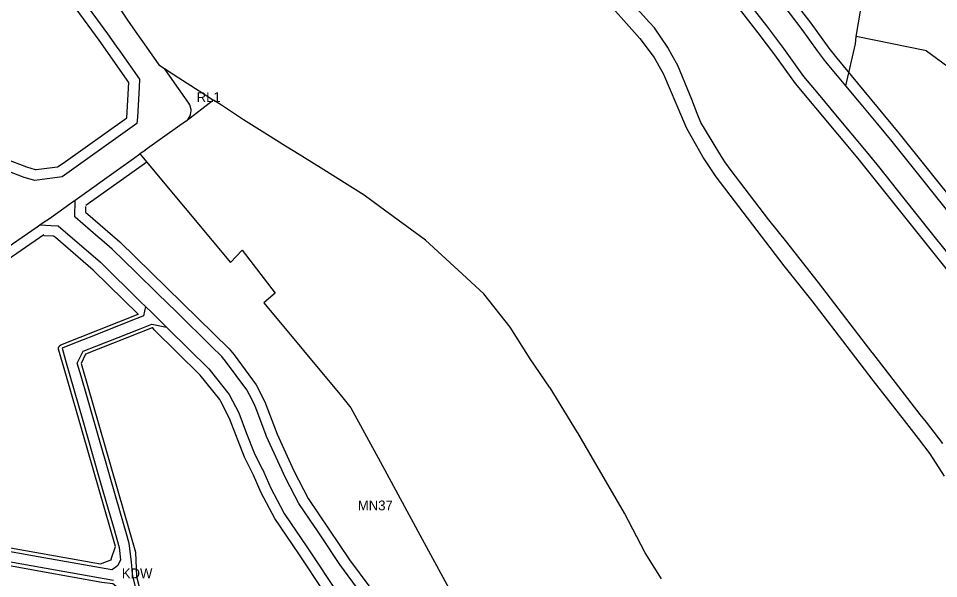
# Model space of a CAD drawing. Extents: x 7428103 to 7431580, y 5545880 to 5549002.
# Drawn here: x 7430217 to 7430738, y 5546912 to 5547228 of the extents above; entities that cross this region are included whole.
import ezdxf

# ---------------------------------------------------------------- set-up
doc = ezdxf.new("R2010")
doc.units = 0
for name, color, linetype in [('CZ_L_linie rozgraniczające tereny o różnym przeznaczeniu oraz różnych warunkach ich zabudowy i zagospodarowania', 7, 'Continuous'), ('CZ_L_maksymalne nieprzekraczalne linie zabudowy', 7, 'Continuous'), ('CZ_L_opisy_linie rozgraniczające tereny o różnym przeznaczeniu oraz różnych warunkach ich zabudowy i zagospodarowania', 7, 'Continuous')]:
    doc.layers.add(name, color=color, linetype=linetype)

msp = doc.modelspace()

# ---------------------------------------------------------------- linework, layer by layer
at = {"layer": 'CZ_L_linie rozgraniczające tereny o różnym przeznaczeniu oraz różnych warunkach ich zabudowy i zagospodarowania'}
for p, q in [((7430212.67, 5547295.01), (7430267.72, 5547219.77)), ((7430691.24, 5547218.28), (7430696.26, 5547247.28)), ((7430629.65, 5547238.08), (7430640.5, 5547224.17)), ((7430660.77, 5547222.18), (7430647.47, 5547239.67)), ((7430274.38, 5547234.22), (7430279.05, 5547227.49)), ((7430553.53, 5547234.13), (7430561.35, 5547225.52)), ((7430574.28, 5547226.17), (7430567.4, 5547233.85)), ((7430279.05, 5547227.49), (7430283.4, 5547221.22)), ((7430561.35, 5547225.52), (7430568.82, 5547217.12)), ((7430577.08, 5547223.04), (7430574.28, 5547226.17)), ((7430283.4, 5547221.22), (7430289.75, 5547212.08)), ((7430584.64, 5547212.05), (7430577.08, 5547223.04)), ((7430640.5, 5547224.17), (7430650.12, 5547211.32)), ((7430669.43, 5547210.13), (7430660.77, 5547222.18)), ((7430267.72, 5547219.77), (7430272.66, 5547212.75)), ((7430568.82, 5547217.12), (7430576.93, 5547206.31)), ((7430690.94, 5547214.14), (7430691.24, 5547218.28)), ((7430731.04, 5547210.13), (7430691.24, 5547218.28)), ((7430272.66, 5547212.75), (7430274.72, 5547209.82)), ((7430274.72, 5547209.82), (7430285.86, 5547194.01)), ((7430289.75, 5547212.08), (7430296.63, 5547202.17)), ((7430587.23, 5547207.47), (7430584.64, 5547212.05)), ((7430650.12, 5547211.32), (7430661.48, 5547195.53)), ((7430673.89, 5547204.06), (7430669.43, 5547210.13)), ((7430685.45, 5547190.23), (7430690.94, 5547214.14)), ((7430731, 5547209.91), (7430731.04, 5547210.13)), ((7430746.02, 5547199.03), (7430731, 5547209.91)), ((7430576.93, 5547206.31), (7430582.32, 5547196.97)), ((7430590.35, 5547201.86), (7430587.23, 5547207.47)), ((7430296.63, 5547202.17), (7430299.94, 5547200.07)), ((7430299.94, 5547200.07), (7430308.09, 5547194.89)), ((7430598.18, 5547182.53), (7430590.35, 5547201.86)), ((7430680.6, 5547196.03), (7430673.89, 5547204.06)), ((7430308.09, 5547194.89), (7430319.59, 5547187.56)), ((7430582.32, 5547196.97), (7430592.98, 5547171.71)), ((7430661.48, 5547195.53), (7430669.68, 5547185.71)), ((7430685.45, 5547190.23), (7430680.6, 5547196.03)), ((7430285.56, 5547189.32), (7430284.67, 5547172.63)), ((7430285.86, 5547194.01), (7430285.56, 5547189.32)), ((7430693.07, 5547181.11), (7430685.45, 5547190.23)), ((7430319.59, 5547187.56), (7430327.65, 5547182.26)), ((7430669.68, 5547185.71), (7430680.43, 5547172.85)), ((7430327.65, 5547182.26), (7430312, 5547170.24)), ((7430332.14, 5547179.31), (7430327.65, 5547182.26)), ((7430344.63, 5547171.1), (7430332.14, 5547179.31)), ((7430601.33, 5547174.76), (7430598.18, 5547182.53)), ((7430703.47, 5547168.66), (7430693.07, 5547181.11)), ((7430603.45, 5547169.52), (7430601.33, 5547174.76)), ((7430284.3, 5547168.95), (7430241.96, 5547138.87)), ((7430284.67, 5547172.63), (7430284.3, 5547168.95)), ((7430311.87, 5547170.15), (7430307.34, 5547166.92)), ((7430311.95, 5547170.21), (7430311.87, 5547170.15)), ((7430312, 5547170.24), (7430311.95, 5547170.21)), ((7430358.25, 5547162.54), (7430344.63, 5547171.1)), ((7430592.98, 5547171.71), (7430595.2, 5547166.46)), ((7430606.07, 5547165.24), (7430603.45, 5547169.52)), ((7430680.43, 5547172.85), (7430696.82, 5547153.23)), ((7430711.58, 5547158.94), (7430703.47, 5547168.66)), ((7430307.3, 5547166.89), (7430295.67, 5547158.63)), ((7430307.34, 5547166.92), (7430307.3, 5547166.89)), ((7430595.2, 5547166.46), (7430605.02, 5547149.12)), ((7430614.18, 5547151.8), (7430606.07, 5547165.24)), ((7430295.67, 5547158.63), (7430288.98, 5547153.88)), ((7430368.34, 5547156.29), (7430358.25, 5547162.54)), ((7430716.84, 5547152.34), (7430711.58, 5547158.94)), ((7430288.95, 5547153.85), (7430286.06, 5547151.81)), ((7430288.98, 5547153.88), (7430288.95, 5547153.85)), ((7430373.71, 5547152.95), (7430368.34, 5547156.29)), ((7430388.49, 5547143.78), (7430373.71, 5547152.95)), ((7430696.82, 5547153.23), (7430704.54, 5547143.71)), ((7430220.62, 5547138.54), (7430195.21, 5547148.12)), ((7430273.98, 5547143.22), (7430282.38, 5547149.19)), ((7430282.38, 5547149.19), (7430282.46, 5547149.26)), ((7430282.46, 5547149.26), (7430286.06, 5547151.81)), ((7430286.06, 5547151.81), (7430337.18, 5547090.38)), ((7430605.02, 5547149.12), (7430611.9, 5547138.93)), ((7430616.86, 5547147.35), (7430614.18, 5547151.8)), ((7430620.54, 5547142.52), (7430616.86, 5547147.35)), ((7430726.71, 5547139.98), (7430716.84, 5547152.34)), ((7430249.37, 5547125.74), (7430273.98, 5547143.22)), ((7430412.85, 5547128.44), (7430388.49, 5547143.78)), ((7430641.91, 5547114.51), (7430620.54, 5547142.52)), ((7430704.54, 5547143.71), (7430717.38, 5547127.62)), ((7430226.55, 5547136.8), (7430220.62, 5547138.54)), ((7430241.96, 5547138.87), (7430226.55, 5547136.8)), ((7430611.9, 5547138.93), (7430650.34, 5547088.54)), ((7430737.11, 5547126.94), (7430726.71, 5547139.98)), ((7430421.52, 5547122.12), (7430412.85, 5547128.44)), ((7430717.38, 5547127.62), (7430734.48, 5547106.2)), ((7430742.39, 5547120.33), (7430737.11, 5547126.94)), ((7430242.96, 5547121.18), (7430248.43, 5547125.07)), ((7430248.43, 5547125.07), (7430248.9, 5547125.4)), ((7430248.9, 5547125.4), (7430249.33, 5547125.7)), ((7430249.17, 5547116.22), (7430249.33, 5547125.7)), ((7430249.33, 5547125.7), (7430249.37, 5547125.74)), ((7430447.52, 5547103.14), (7430421.52, 5547122.12)), ((7430234.78, 5547115.41), (7430242.88, 5547121.11)), ((7430242.88, 5547121.11), (7430242.96, 5547121.18)), ((7430249.19, 5547116.2), (7430249.17, 5547116.22)), ((7430249.3, 5547116.1), (7430249.19, 5547116.2)), ((7430262.41, 5547104.83), (7430249.3, 5547116.1)), ((7430227.89, 5547110.67), (7430229.47, 5547111.75)), ((7430229.47, 5547111.75), (7430231.82, 5547113.37)), ((7430229.47, 5547111.75), (7430235.72, 5547111.38)), ((7430231.82, 5547113.37), (7430234.77, 5547115.4)), ((7430234.77, 5547115.4), (7430234.77, 5547115.41)), ((7430234.77, 5547115.41), (7430234.78, 5547115.41)), ((7430235.72, 5547111.38), (7430239.75, 5547111.13)), ((7430239.75, 5547111.13), (7430263.65, 5547090.57)), ((7430651.95, 5547102), (7430641.91, 5547114.51)), ((7430186.16, 5547081.91), (7430227.89, 5547110.67)), ((7430734.48, 5547106.2), (7430748.41, 5547088.89)), ((7430264.46, 5547103.07), (7430262.41, 5547104.83)), ((7430270.3, 5547098.04), (7430264.46, 5547103.07)), ((7430466.04, 5547086.19), (7430447.52, 5547103.14)), ((7430660.92, 5547090.58), (7430651.95, 5547102)), ((7430270.39, 5547097.92), (7430270.3, 5547098.04)), ((7430270.53, 5547097.83), (7430270.39, 5547097.92)), ((7430283.49, 5547085.16), (7430270.53, 5547097.83)), ((7430337.18, 5547090.38), (7430343.87, 5547097.36)), ((7430343.87, 5547097.36), (7430362.49, 5547073.08)), ((7430263.65, 5547090.57), (7430286.41, 5547068.31)), ((7430669.94, 5547079.13), (7430660.92, 5547090.58)), ((7430296.1, 5547072.82), (7430283.49, 5547085.16)), ((7430480.56, 5547072.8), (7430466.04, 5547086.19)), ((7430650.34, 5547088.54), (7430666.18, 5547068.85)), ((7430692.81, 5547049.44), (7430669.94, 5547079.13)), ((7430306.65, 5547062.49), (7430296.1, 5547072.82)), ((7430362.49, 5547073.08), (7430356.04, 5547067.71)), ((7430495.45, 5547053.89), (7430480.56, 5547072.8)), ((7430286.41, 5547068.31), (7430289.19, 5547065.58)), ((7430289.19, 5547065.58), (7430288.06, 5547060.24)), ((7430292.75, 5547062.1), (7430289.19, 5547065.58)), ((7430356.04, 5547067.71), (7430400.03, 5547014.84)), ((7430666.18, 5547068.85), (7430683.58, 5547046.14)), ((7430284.84, 5547058.96), (7430282.8, 5547058.16)), ((7430288.06, 5547060.24), (7430284.84, 5547058.96)), ((7430297.47, 5547057.48), (7430292.75, 5547062.1)), ((7430306.66, 5547062.49), (7430306.65, 5547062.49)), ((7430306.66, 5547062.48), (7430306.66, 5547062.49)), ((7430326.59, 5547042.92), (7430306.66, 5547062.48)), ((7430282.8, 5547058.16), (7430259.73, 5547049.02)), ((7430286.2, 5547053.05), (7430288.08, 5547053.79)), ((7430288.08, 5547053.79), (7430292.77, 5547055.63)), ((7430292.77, 5547055.63), (7430301.11, 5547053.91)), ((7430301.11, 5547053.91), (7430297.47, 5547057.48)), ((7430301.11, 5547053.91), (7430302, 5547053.05)), ((7430506.88, 5547036.04), (7430495.45, 5547053.89)), ((7430259.73, 5547049.02), (7430248.09, 5547044.41)), ((7430273.79, 5547048.14), (7430286.2, 5547053.05)), ((7430302, 5547053.05), (7430325.08, 5547030.39)), ((7430700.35, 5547039.64), (7430692.81, 5547049.44)), ((7430248.09, 5547044.41), (7430241.94, 5547042.03)), ((7430253.91, 5547040.26), (7430261.6, 5547043.31)), ((7430261.6, 5547043.31), (7430273.79, 5547048.14)), ((7430683.58, 5547046.14), (7430700.73, 5547023.82)), ((7430241.94, 5547042.03), (7430244.32, 5547033.66)), ((7430250.6, 5547033.56), (7430253.91, 5547040.26)), ((7430332.31, 5547037.31), (7430326.59, 5547042.92)), ((7430700.63, 5547039.28), (7430700.35, 5547039.64)), ((7430715.32, 5547020.17), (7430700.63, 5547039.28)), ((7430244.32, 5547033.66), (7430246.35, 5547026.52)), ((7430252.73, 5547026.16), (7430250.6, 5547033.56)), ((7430332.35, 5547037.25), (7430332.31, 5547037.31)), ((7430332.72, 5547036.85), (7430332.35, 5547037.25)), ((7430334.51, 5547034.6), (7430332.72, 5547036.85)), ((7430346.48, 5547018.5), (7430334.51, 5547034.6)), ((7430517.67, 5547020), (7430506.88, 5547036.04)), ((7430325.08, 5547030.39), (7430336.58, 5547015.88)), ((7430246.35, 5547026.52), (7430253.7, 5547001.07)), ((7430256.27, 5547013.86), (7430252.73, 5547026.16)), ((7430700.73, 5547023.82), (7430718.34, 5547001.14)), ((7430347.95, 5547015.65), (7430346.48, 5547018.5)), ((7430518.08, 5547019.52), (7430517.67, 5547020)), ((7430533.6, 5546994.45), (7430518.08, 5547019.52)), ((7430727.39, 5547004.45), (7430715.32, 5547020.17)), ((7430263.11, 5546990.06), (7430256.27, 5547013.86)), ((7430336.58, 5547015.88), (7430341.98, 5547005.42)), ((7430351, 5547009.74), (7430347.95, 5547015.65)), ((7430400.03, 5547014.84), (7430405.25, 5547008.39)), ((7430351.07, 5547009.45), (7430351, 5547009.74)), ((7430351.23, 5547009.23), (7430351.07, 5547009.45)), ((7430357.26, 5546993.31), (7430351.23, 5547009.23)), ((7430405.25, 5547008.39), (7430421.95, 5546977.92)), ((7430341.98, 5547005.42), (7430346.36, 5546993.86)), ((7430731.1, 5547000.24), (7430727.39, 5547004.45)), ((7430253.7, 5547001.07), (7430259.44, 5546981.09)), ((7430718.34, 5547001.14), (7430726.24, 5546990.95)), ((7430737.75, 5546991.41), (7430731.1, 5547000.24)), ((7430346.36, 5546993.86), (7430350.64, 5546982.93)), ((7430357.69, 5546992.16), (7430357.26, 5546993.31)), ((7430368.33, 5546968.65), (7430357.69, 5546992.16)), ((7430533.71, 5546994.25), (7430533.6, 5546994.45)), ((7430540.01, 5546983.39), (7430533.71, 5546994.25)), ((7430740.2, 5546988.17), (7430737.75, 5546991.41)), ((7430266.48, 5546978.32), (7430263.11, 5546990.06)), ((7430726.24, 5546990.95), (7430732.96, 5546982.28)), ((7430259.44, 5546981.09), (7430263.42, 5546967.23)), ((7430350.64, 5546982.93), (7430355.26, 5546973.58)), ((7430560.1, 5546948.76), (7430540.01, 5546983.39)), ((7430732.96, 5546982.28), (7430740.94, 5546969.76)), ((7430272.51, 5546957.34), (7430266.48, 5546978.32)), ((7430421.95, 5546977.92), (7430445.69, 5546934.1)), ((7430355.26, 5546973.58), (7430355.37, 5546973.55)), ((7430355.37, 5546973.55), (7430356.1, 5546971.88)), ((7430356.1, 5546971.88), (7430360.01, 5546962.99)), ((7430263.42, 5546967.23), (7430268.07, 5546951.06)), ((7430373.58, 5546958.64), (7430368.33, 5546968.65)), ((7430360.01, 5546962.99), (7430367.16, 5546949.35)), ((7430274.22, 5546951.39), (7430272.51, 5546957.34)), ((7430375.88, 5546954.25), (7430373.58, 5546958.64)), ((7430268.07, 5546951.06), (7430271.01, 5546940.85)), ((7430278.71, 5546935.78), (7430274.22, 5546951.39)), ((7430385.09, 5546940.7), (7430375.88, 5546954.25)), ((7430367.16, 5546949.35), (7430367.22, 5546949.27)), ((7430367.22, 5546949.27), (7430367.45, 5546948.86)), ((7430367.45, 5546948.86), (7430367.98, 5546948.09)), ((7430367.98, 5546948.09), (7430380.39, 5546929.81)), ((7430571.79, 5546926.26), (7430560.1, 5546948.76)), ((7430271.01, 5546940.85), (7430274.35, 5546929.42)), ((7430385.26, 5546940.45), (7430385.09, 5546940.7)), ((7430388.68, 5546935.41), (7430385.26, 5546940.45)), ((7430279.9, 5546931.7), (7430278.71, 5546935.78)), ((7430388.69, 5546935.39), (7430388.68, 5546935.41)), ((7430388.7, 5546935.38), (7430388.69, 5546935.39)), ((7430399.09, 5546919.79), (7430388.7, 5546935.38)), ((7430445.69, 5546934.1), (7430464.79, 5546899.07)), ((7430271.15, 5546910.68), (7430161.61, 5546930.19)), ((7430228.48, 5546924.09), (7430177.87, 5546933.33)), ((7430274.35, 5546929.42), (7430274.94, 5546922.47)), ((7430281.33, 5546921.21), (7430279.9, 5546931.7)), ((7430380.39, 5546929.81), (7430384.6, 5546923.5)), ((7430270.15, 5546916.8), (7430228.48, 5546924.09)), ((7430384.6, 5546923.5), (7430395.32, 5546907.4)), ((7430581.04, 5546911.62), (7430571.79, 5546926.26)), ((7430273.46, 5546919.1), (7430271.63, 5546917.62)), ((7430274.94, 5546922.47), (7430273.46, 5546919.1)), ((7430281.73, 5546914.4), (7430281.33, 5546921.21)), ((7430411.21, 5546903.4), (7430399.09, 5546919.79)), ((7430271.63, 5546917.62), (7430270.15, 5546916.8)), ((7430282.23, 5546912.41), (7430281.73, 5546914.4)), ((7430285.53, 5546899.31), (7430282.23, 5546912.41))]:
    msp.add_line(p, q, dxfattribs=at)
for points in [[(7430312, 5547170.24), (7430312.93, 5547171.07), (7430313.04, 5547171.18), (7430313.22, 5547171.41), (7430314.44, 5547173.41), (7430314.57, 5547173.67), (7430314.64, 5547173.96), (7430314.98, 5547176.12), (7430315.01, 5547176.27), (7430315.02, 5547176.56), (7430314.98, 5547176.86), (7430314.5, 5547178.86), (7430314.43, 5547179.13), (7430314.34, 5547179.41), (7430314.28, 5547179.53), (7430313.74, 5547180.46), (7430313.71, 5547180.5), (7430313.66, 5547180.58), (7430305.67, 5547191.92), (7430299.94, 5547200.07)], [(7430311.87, 5547170.15), (7430311.95, 5547170.21)], [(7430311.95, 5547170.21), (7430312, 5547170.24)]]:
    msp.add_lwpolyline(points, dxfattribs=at)
at = {"layer": 'CZ_L_maksymalne nieprzekraczalne linie zabudowy'}
for points in [[(7430197.83, 5547153.55), (7430221.84, 5547144.49), (7430226.69, 5547143.01), (7430227.3, 5547142.95), (7430239.41, 5547144.58), (7430242.53, 5547146.63), (7430278.61, 5547172.29), (7430279.73, 5547192.13), (7430263, 5547216.05), (7430210.93, 5547287.22)], [(7430654.54, 5547240.29), (7430665.61, 5547225.73), (7430675.78, 5547211.67), (7430680.29, 5547205.95), (7430715.45, 5547163.65), (7430765.79, 5547100.82), (7430780.35, 5547083.28), (7430800.05, 5547059.92), (7430816.12, 5547041.16), (7430824.8, 5547031.35), (7430886.76, 5546964.98), (7430896.64, 5546952.97), (7430901.69, 5546945.24), (7430901.95, 5546945.2), (7430902.39, 5546945.93), (7430903.3, 5546948.81), (7430911.71, 5546982.58), (7430913.18, 5546988.55), (7430923.67, 5547028.55), (7430938.24, 5547068.96)], [(7430743.74, 5547085.12), (7430692.31, 5547149.26), (7430656.87, 5547191.68), (7430645.29, 5547207.77), (7430635.89, 5547220.31), (7430625.29, 5547233.91)], [(7430289.96, 5547147.22), (7430255.33, 5547122.61)], [(7430255.27, 5547122.04), (7430255.22, 5547118.96), (7430274.72, 5547102.13), (7430336.52, 5547041.58), (7430339.32, 5547038.18), (7430351.81, 5547021.26), (7430356.67, 5547011.75), (7430363.71, 5546993.43), (7430373.05, 5546972.78), (7430381.25, 5546957.03), (7430404.58, 5546922.46), (7430416.08, 5546906.9), (7430427.66, 5546892.23), (7430428.81, 5546890.43), (7430438, 5546871.09), (7430448.65, 5546840.38), (7430458.81, 5546792.97), (7430463.86, 5546755.45), (7430465.89, 5546736.87), (7430470.41, 5546705.09), (7430470.39, 5546686.55), (7430470.1, 5546675.12), (7430471.75, 5546671.83), (7430495.88, 5546660.27)], [(7430231.7, 5547106), (7430123.4, 5547031.46), (7430088.38, 5547011.55), (7430085.68, 5547010.48), (7430084.65, 5547007.98), (7430084.68, 5547007.5), (7430095.42, 5546985.4), (7430112.43, 5546951.18), (7430114.48, 5546947.07), (7430115.24, 5546946.15), (7430163.72, 5546938.19), (7430192.49, 5546932.83), (7430263.64, 5546920.06), (7430270.09, 5546922.66)], [(7430285.15, 5547061.14), (7430259.6, 5547086.15), (7430238.26, 5547104.5), (7430237.14, 5547105.28), (7430231.57, 5547105.62)], [(7430269.76, 5546922.77), (7430272.13, 5546929.91), (7430244.42, 5547025.97), (7430240.01, 5547041.48), (7430239.95, 5547042.21), (7430240.31, 5547043.18), (7430241.19, 5547043.88), (7430284.97, 5547061.17)], [(7430390.48, 5546903.87), (7430375.93, 5546925.7), (7430362.37, 5546945.67), (7430354.68, 5546960.22), (7430350.26, 5546970.28), (7430345.19, 5546980.41), (7430336.74, 5547002.31), (7430331.86, 5547011.95), (7430331.19, 5547013.03), (7430320.15, 5547026.82), (7430294.04, 5547052.44), (7430293.3, 5547053.48), (7430292.96, 5547053.55), (7430255.3, 5547038.57), (7430252.74, 5547033.37), (7430283.44, 5546926.71), (7430284.17, 5546912.9), (7430294.11, 5546874.27)], [(7430216.39, 5546767.17), (7430255.6, 5546758.2), (7430277.54, 5546752.43), (7430298.01, 5546746.29), (7430318.21, 5546739.19), (7430317.16, 5546745.72), (7430310.75, 5546769.28), (7430301.85, 5546799.08), (7430298.02, 5546813.63), (7430293.79, 5546833.91), (7430284.4, 5546871.86), (7430275.92, 5546904.73), (7430270.67, 5546908.79), (7430264.52, 5546909.65), (7430230.85, 5546915.6), (7430156.13, 5546929.21)]]:
    msp.add_lwpolyline(points, dxfattribs=at)

# ---------------------------------------------------------------- texts
at = {"layer": 'CZ_L_opisy_linie rozgraniczające tereny o różnym przeznaczeniu oraz różnych warunkach ich zabudowy i zagospodarowania'}
for s, p in [('RL1', (7430318.1, 5547181.17)), ('MN37', (7430409.29, 5546950.37)), ('KDW', (7430275.76, 5546911.98))]:
    msp.add_text(s, height=5.549, dxfattribs=at).set_placement(p)

doc.saveas('drawing.dxf')
